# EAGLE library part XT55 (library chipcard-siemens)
XT55 Siemens Cellular Engine Source: Siemens / xt55_hardW_v0100.pdf
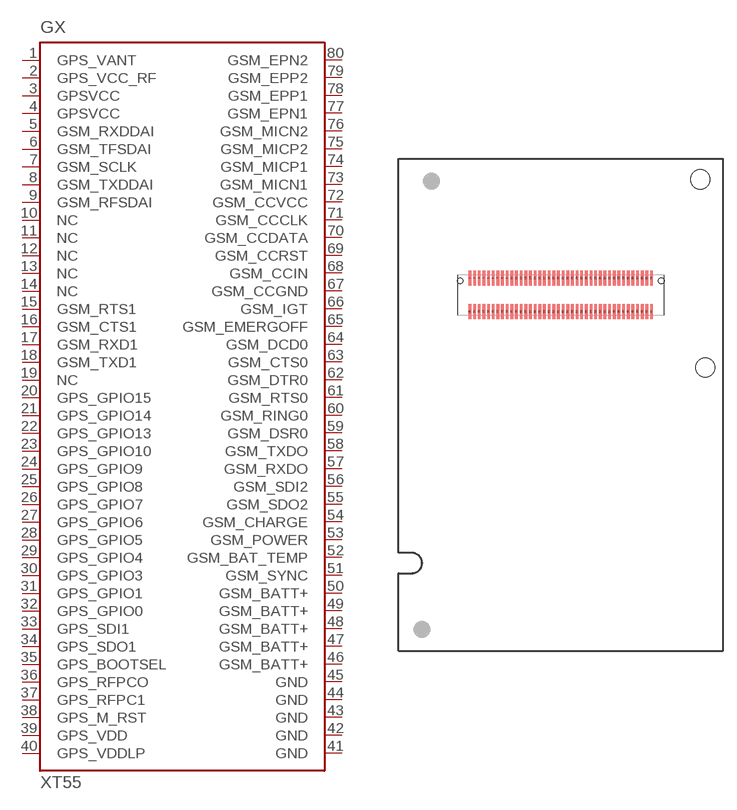
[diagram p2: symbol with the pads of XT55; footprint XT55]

Designator prefix GX

## XT55 (OC_FARNELL: unknown; OC_NEWARK: unknown)  [XT55]
1  GPS_VANT  pas
2  GPS_VCC_RF  pas
3  GPSVCC  pas
4  GPSVCC  pas
5  GSM_RXDDAI  pas
6  GSM_TFSDAI  pas
7  GSM_SCLK  pas
8  GSM_TXDDAI  pas
9  GSM_RFSDAI  pas
10  NC  pas
11  NC  pas
12  NC  pas
13  NC  pas
14  NC  pas
15  GSM_RTS1  pas
16  GSM_CTS1  pas
17  GSM_RXD1  pas
18  GSM_TXD1  pas
19  NC  pas
20  GPS_GPIO15  pas
21  GPS_GPIO14  pas
22  GPS_GPIO13  pas
23  GPS_GPIO10  pas
24  GPS_GPIO9  pas
25  GPS_GPIO8  pas
26  GPS_GPIO7  pas
27  GPS_GPIO6  pas
28  GPS_GPIO5  pas
29  GPS_GPIO4  pas
30  GPS_GPIO3  pas
31  GPS_GPIO1  pas
32  GPS_GPIO0  pas
33  GPS_SDI1  pas
34  GPS_SDO1  pas
35  GPS_BOOTSEL  pas
36  GPS_RFPCO  pas
37  GPS_RFPC1  pas
38  GPS_M_RST  pas
39  GPS_VDD  pas
40  GPS_VDDLP  pas
41  GND  pas
42  GND  pas
43  GND  pas
44  GND  pas
45  GND  pas
46  GSM_BATT+  pas
47  GSM_BATT+  pas
48  GSM_BATT+  pas
49  GSM_BATT+  pas
50  GSM_BATT+  pas
51  GSM_SYNC  pas
52  GSM_BAT_TEMP  pas
53  GSM_POWER  pas
54  GSM_CHARGE  pas
55  GSM_SDO2  pas
56  GSM_SDI2  pas
57  GSM_RXDO  pas
58  GSM_TXDO  pas
59  GSM_DSR0  pas
60  GSM_RING0  pas
61  GSM_RTS0  pas
62  GSM_DTR0  pas
63  GSM_CTS0  pas
64  GSM_DCD0  pas
65  GSM_EMERGOFF  pas
66  GSM_IGT  pas
67  GSM_CCGND  pas
68  GSM_CCIN  pas
69  GSM_CCRST  pas
70  GSM_CCDATA  pas
71  GSM_CCCLK  pas
72  GSM_CCVCC  pas
73  GSM_MICN1  pas
74  GSM_MICP1  pas
75  GSM_MICP2  pas
76  GSM_MICN2  pas
77  GSM_EPN1  pas
78  GSM_EPP1  pas
79  GSM_EPP2  pas
80  GSM_EPN2  pas

## Footprint XT55 (pad centres in mm)
XT55 Siemens Cellular Engine Connector DF12-80 from Hirose Source: Siemens / xt55_hardW_v0100.pdf HIROSE - DF12D(3.0)-#DP-0.5V(81).pdf
smd 0.3 x 1.6: 1 -9.75,1.8; 2 -9.25,1.8; 3 -8.75,1.8; 4 -8.25,1.8; 5 -7.75,1.8; 6 -7.25,1.8; 7 -6.75,1.8; 8 -6.25,1.8; 9 -5.75,1.8; 10 -5.25,1.8; 11 -4.75,1.8; 12 -4.25,1.8; 13 -3.75,1.8; 14 -3.25,1.8; 15 -2.75,1.8; 16 -2.25,1.8; 17 -1.75,1.8; 18 -1.25,1.8; 19 -0.75,1.8; 20 -0.25,1.8; 21 0.25,1.8; 22 0.75,1.8; 23 1.25,1.8; 24 1.75,1.8; 25 2.25,1.8; 26 2.75,1.8; 27 3.25,1.8; 28 3.75,1.8; 29 4.25,1.8; 30 4.75,1.8; 31 5.25,1.8; 32 5.75,1.8; 33 6.25,1.8; 34 6.75,1.8; 35 7.25,1.8; 36 7.75,1.8; 37 8.25,1.8; 38 8.75,1.8; 39 9.25,1.8; 40 9.75,1.8; 41 9.75,-1.8; 42 9.25,-1.8; 43 8.75,-1.8; 44 8.25,-1.8; 45 7.75,-1.8; 46 7.25,-1.8; 47 6.75,-1.8; 48 6.25,-1.8; 49 5.75,-1.8; 50 5.25,-1.8; 51 4.75,-1.8; 52 4.25,-1.8; 53 3.75,-1.8; 54 3.25,-1.8; 55 2.75,-1.8; 56 2.25,-1.8; 57 1.75,-1.8; 58 1.25,-1.8; 59 0.75,-1.8; 60 0.25,-1.8; 61 -0.25,-1.8; 62 -0.75,-1.8; 63 -1.25,-1.8; 64 -1.75,-1.8; 65 -2.25,-1.8; 66 -2.75,-1.8; 67 -3.25,-1.8; 68 -3.75,-1.8; 69 -4.25,-1.8; 70 -4.75,-1.8; 71 -5.25,-1.8; 72 -5.75,-1.8; 73 -6.25,-1.8; 74 -6.75,-1.8; 75 -7.25,-1.8; 76 -7.75,-1.8; 77 -8.25,-1.8; 78 -8.75,-1.8; 79 -9.25,-1.8; 80 -9.75,-1.8
hole 2.05 at 15,12.4
hole 2.05 at 15.5,-7.8
hole 0.6 at -10.8,1.5
hole 0.6 at 10.8,1.5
